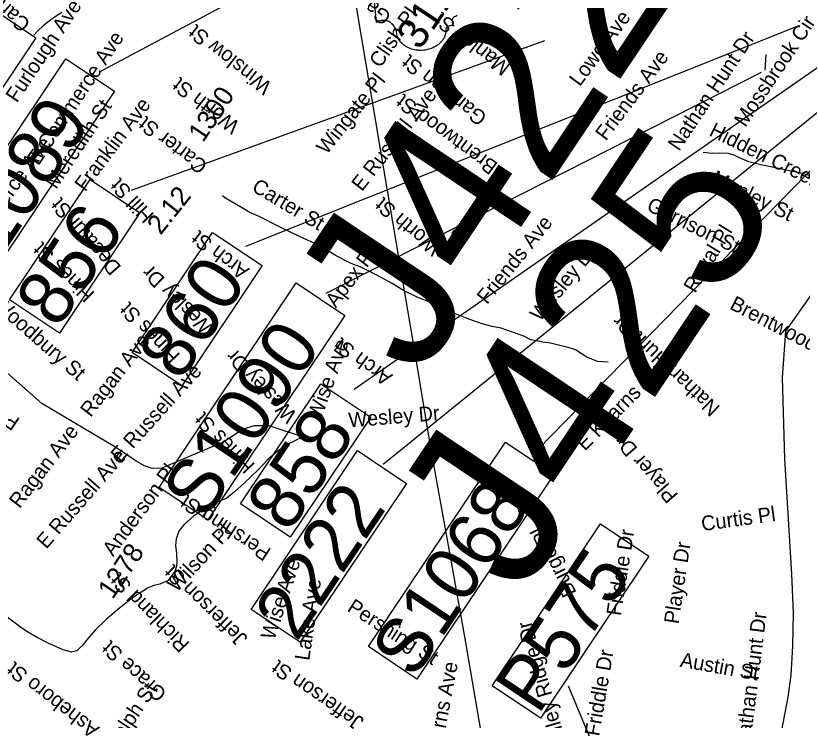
# Model space of a CAD drawing. Extents: x 1716282 to 1717158, y 799307 to 801078.
# Drawn here: x 1716607.4 to 1716680.6, y 799385.8 to 799451.4 of the extents above; entities that cross this region are included whole.
import ezdxf

# ---------------------------------------------------------------- set-up
doc = ezdxf.new("R2010")
doc.units = 0
for name, color, linetype in [('Exist Hydrographic Misc Water Feature', 7, 'Continuous'), ('Exist Road Non-System Structure Non-Sys Other Number Label', 7, 'Continuous'), ('Exist Road Non-System Type 51 Label', 7, 'Continuous'), ('Exist Road Primary Interstate Structure Cantilever Sign Number Label', 7, 'Continuous'), ('Exist Road Primary Interstate Structure Ovrhead Sign CELL', 7, 'Continuous'), ('Exist Road Primary US Shield CELL', 7, 'Continuous'), ('Exist Road Primary US Shield Number Label', 7, 'Continuous'), ('Exist Road Primary US Structure Ovrhead Sign CELL', 7, 'Continuous'), ('Exist Road Primary US Structure Pipe Number Label', 7, 'Continuous'), ('Exist Road Primary US Structure Standard Bridge Number Label', 7, 'Continuous'), ('Exist Road Secondary Mileage Tenths English Label', 7, 'Continuous'), ('Exist Road Secondary Type 51 Number Label', 7, 'Continuous'), ('Exist Utilities Electrical Transmission Line', 7, 'Continuous')]:
    doc.layers.add(name, color=color, linetype=linetype)

msp = doc.modelspace()

# ---------------------------------------------------------------- linework, layer by layer
at = {"layer": 'Exist Hydrographic Misc Water Feature'}
for points in [[(1716611.684, 799451.659), (1716610.792, 799451.073), (1716609.988, 799450.461), (1716609.419, 799449.937), (1716609.092, 799449.564)], [(1716692.169, 799435.567), (1716691.015, 799435.266), (1716690.298, 799435.193), (1716689.237, 799435.286), (1716686.84, 799435.273), (1716684.022, 799435.828), (1716682.215, 799436.217), (1716680.628, 799436.671), (1716678.821, 799437.061), (1716676.606, 799437.52), (1716675.619, 799437.773), (1716674.739, 799438.129), (1716674.251, 799438.392), (1716673.722, 799438.544), (1716672.86, 799438.568), (1716672.216, 799438.551), (1716671.365, 799438.642)], [(1716662.52, 799419.11), (1716661.547, 799419.178), (1716660.553, 799419.574), (1716659.483, 799420.269), (1716658.818, 799420.48), (1716657.92, 799420.707), (1716657.197, 799420.883), (1716656.45, 799420.973), (1716655.341, 799421.202), (1716654.695, 799421.54), (1716652.571, 799422.288), (1716651.728, 799422.442), (1716650.806, 799422.685), (1716649.555, 799423.118), (1716648.001, 799423.724), (1716646.961, 799424.258), (1716646.096, 799424.639), (1716644.815, 799425.128), (1716643.502, 799425.778), (1716642.367, 799426.482), (1716641.135, 799427.147), (1716639.456, 799427.979), (1716638.622, 799428.302), (1716637.934, 799428.632), (1716637.054, 799429.093), (1716636.384, 799429.551), (1716635.656, 799429.977), (1716633.879, 799430.77), (1716632.015, 799431.693), (1716629.991, 799432.69), (1716629.19, 799433.06), (1716628.35, 799433.527), (1716626.872, 799434.397), (1716626.648, 799434.584)], [(1716634.283, 799412.094), (1716631.001, 799413.172), (1716629.589, 799413.174), (1716628.557, 799412.863), (1716626.769, 799411.704), (1716621.009, 799409.256), (1716620.1, 799409.217), (1716619.381, 799409.463), (1716618.622, 799409.912), (1716616.792, 799411.137), (1716609.838, 799415.261), (1716604.726, 799419.771), (1716601.769, 799420.773), (1716598.43, 799420.566), (1716594.486, 799421.653), (1716591.302, 799423.243), (1716585.392, 799426.833), (1716582.572, 799429.941), (1716580.814, 799430.996), (1716580.091, 799431.043)], [(1716634.228, 799412.206), (1716633.177, 799411.687), (1716632.68, 799411.459), (1716631.736, 799410.787), (1716630.876, 799410.041), (1716630.002, 799409.128), (1716628.662, 799407.846), (1716627.768, 799407.051), (1716627.039, 799406.459), (1716625.859, 799405.968), (1716623.987, 799404.82), (1716623.078, 799404.003), (1716622.62, 799403.436), (1716622.346, 799402.675), (1716622.274, 799402.056), (1716622.356, 799401.3), (1716622.394, 799400.534), (1716622.366, 799400.133), (1716622.208, 799399.643), (1716621.594, 799398.798), (1716620.802, 799398.461), (1716620.262, 799398.338), (1716619.664, 799398.079), (1716618.359, 799397.249), (1716617.085, 799396.257), (1716615.809, 799395.161), (1716614.824, 799394.184), (1716614.001, 799393.236), (1716613.65, 799392.773), (1716613.349, 799392.486), (1716613.081, 799392.249), (1716612.604, 799392.117), (1716611.81, 799392.343), (1716610.489, 799392.93), (1716609.336, 799393.505), (1716608.443, 799394.047), (1716607.844, 799394.457), (1716605.562, 799396.154)]]:
    msp.add_lwpolyline(points, dxfattribs=at)
at = {"layer": 'Exist Road Primary Interstate Structure Cantilever Sign Number Label'}
msp.add_lwpolyline([(1716592.464, 799433.288), (1716605.07, 799452.122), (1716609.274, 799449.308), (1716596.669, 799430.474)], close=True, dxfattribs=at)
at = {"layer": 'Exist Road Primary Interstate Structure Ovrhead Sign CELL'}
msp.add_line((1716683.741, 799439.418), (1716655.978, 799410.97), dxfattribs=at)
msp.add_lwpolyline([(1716640.223, 799392.638), (1716652.966, 799411.677), (1716657.474, 799408.659), (1716644.731, 799389.62)], close=True, dxfattribs=at)
at = {"layer": 'Exist Road Primary US Shield CELL'}
msp.add_lwpolyline([(1716648.49, 799451.372), (1716648.381, 799451.309), (1716648.175, 799451.218), (1716648.12, 799451.188), (1716648.096, 799451.167), (1716648.052, 799451.108), (1716648.026, 799451.042), (1716648.01, 799450.968), (1716648.005, 799450.919), (1716648.005, 799450.851), (1716648.009, 799450.796), (1716648.021, 799450.724), (1716648.036, 799450.67), (1716648.048, 799450.629), (1716648.088, 799450.537), (1716648.111, 799450.499), (1716648.143, 799450.454), (1716648.197, 799450.397), (1716648.103, 799450.43), (1716648.034, 799450.442), (1716647.971, 799450.445), (1716647.911, 799450.444), (1716647.83, 799450.434), (1716647.765, 799450.419), (1716647.693, 799450.397), (1716647.628, 799450.367), (1716647.579, 799450.34), (1716647.539, 799450.311), (1716647.497, 799450.273), (1716647.469, 799450.237), (1716647.448, 799450.206), (1716647.43, 799450.156), (1716647.433, 799450.071), (1716647.434, 799449.99), (1716647.431, 799449.906), (1716647.421, 799449.809), (1716647.41, 799449.741), (1716647.393, 799449.663), (1716647.369, 799449.574), (1716647.336, 799449.482), (1716647.298, 799449.39), (1716647.262, 799449.311), (1716647.218, 799449.23), (1716647.174, 799449.16), (1716647.125, 799449.089), (1716647.075, 799449.025), (1716647.016, 799448.952), (1716646.937, 799448.864), (1716646.865, 799448.796), (1716646.785, 799448.727), (1716646.7, 799448.658), (1716646.602, 799448.589), (1716646.473, 799448.506), (1716646.378, 799448.453), (1716646.219, 799448.375), (1716646.015, 799448.294), (1716645.847, 799448.242), (1716645.717, 799448.21), (1716645.512, 799448.171), (1716645.383, 799448.154), (1716645.162, 799448.139), (1716645.009, 799448.137), (1716644.901, 799448.142), (1716644.731, 799448.157), (1716644.628, 799448.172), (1716644.482, 799448.2), (1716644.353, 799448.231), (1716644.233, 799448.265), (1716644.159, 799448.29), (1716644.033, 799448.339), (1716643.945, 799448.377), (1716643.829, 799448.434), (1716643.711, 799448.501), (1716643.606, 799448.569), (1716643.522, 799448.63), (1716643.428, 799448.707), (1716643.332, 799448.795), (1716643.255, 799448.877), (1716643.201, 799448.939), (1716643.139, 799449.02), (1716643.075, 799449.116), (1716643.018, 799449.215), (1716642.975, 799449.302), (1716642.933, 799449.404), (1716642.902, 799449.497), (1716642.875, 799449.61), (1716642.855, 799449.721), (1716642.846, 799449.818), (1716642.823, 799449.94), (1716642.805, 799450.008), (1716642.775, 799450.096), (1716642.743, 799450.171), (1716642.712, 799450.234), (1716642.663, 799450.323), (1716642.623, 799450.384), (1716642.557, 799450.471), (1716642.506, 799450.527), (1716642.438, 799450.594), (1716642.371, 799450.653), (1716642.282, 799450.718), (1716642.205, 799450.766), (1716642.11, 799450.816), (1716642.014, 799450.856), (1716641.926, 799450.886), (1716641.82, 799450.911), (1716641.739, 799450.923), (1716641.622, 799450.93), (1716641.508, 799450.928), (1716641.406, 799450.914), (1716641.312, 799450.895), (1716641.233, 799450.869), (1716641.161, 799450.842), (1716641.078, 799450.803), (1716641.005, 799450.761), (1716640.963, 799450.732), (1716640.8, 799452.696)], dxfattribs=at)
at = {"layer": 'Exist Road Primary US Structure Ovrhead Sign CELL'}
for p, q in [((1716643.573, 799461.232), (1716615.223, 799446.15)), ((1716677.151, 799446.297), (1716677.241, 799447.762)), ((1716676.775, 799446.089), (1716636.262, 799425.501))]:
    msp.add_line(p, q, dxfattribs=at)
for points in [[(1716599.331, 799428.313), (1716612.075, 799447.352), (1716616.583, 799444.335), (1716603.84, 799425.296)], [(1716620.762, 799407.449), (1716633.505, 799426.488), (1716638.014, 799423.471), (1716625.27, 799404.432)]]:
    msp.add_lwpolyline(points, close=True, dxfattribs=at)
at = {"layer": 'Exist Road Primary US Structure Pipe Number Label'}
msp.add_line((1716674.439, 799352.144), (1716658.834, 799388.944), dxfattribs=at)
msp.add_lwpolyline([(1716651.738, 799388.997), (1716661.815, 799404.053), (1716666.309, 799401.045), (1716656.232, 799385.989)], close=True, dxfattribs=at)
at = {"layer": 'Exist Road Primary US Structure Standard Bridge Number Label'}
for p, q in [((1716680.183, 799450.387), (1716628.78, 799429.868)), ((1716686.891, 799449.917), (1716638.887, 799416.575)), ((1716656.608, 799449.038), (1716618.161, 799435.086)), ((1716687.045, 799446.435), (1716641.591, 799409.591))]:
    msp.add_line(p, q, dxfattribs=at)
for points in [[(1716606.841, 799424.91), (1716614.333, 799436.105), (1716618.962, 799433.007), (1716611.469, 799421.813)], [(1716618.229, 799420.001), (1716625.721, 799431.195), (1716630.35, 799428.097), (1716622.857, 799416.903)], [(1716628.318, 799405.913), (1716635.81, 799417.107), (1716640.439, 799414.009), (1716632.947, 799402.815)], [(1716629.316, 799396.086), (1716639.218, 799410.879), (1716643.774, 799407.83), (1716633.872, 799393.036)]]:
    msp.add_lwpolyline(points, close=True, dxfattribs=at)
at = {"layer": 'Exist Utilities Electrical Transmission Line'}
for points in [[(1716665.164, 799344.443), (1716665.563, 799347.513), (1716666.118, 799351.428), (1716663.285, 799358.348), (1716660.01, 799365.081), (1716656.683, 799371.286), (1716651.135, 799382.119), (1716649.283, 799393.013), (1716647.919, 799400.679), (1716645.991, 799411.31), (1716644.572, 799419.966), (1716643.666, 799425.239), (1716641.374, 799438.762), (1716638.601, 799455.36), (1716638.051, 799459.861), (1716636.812, 799466.701), (1716635.068, 799476.572), (1716633.977, 799482.851), (1716632.367, 799492.558)], [(1716680.26, 799334.339), (1716680.764, 799335.057), (1716680.185, 799337.535), (1716678.331, 799344.799), (1716676.348, 799350.042), (1716675.432, 799352.434), (1716672.456, 799359.805), (1716671.861, 799361.346), (1716670.155, 799367.243), (1716673.875, 799374.217), (1716676.633, 799379.291), (1716678.11, 799382.043), (1716678.698, 799384.843), (1716679.28, 799387.925), (1716679.571, 799389.979), (1716679.706, 799392.689), (1716679.774, 799395.79), (1716679.635, 799399.371), (1716678.984, 799410.108), (1716678.759, 799417.692), (1716679.055, 799422.002), (1716682.293, 799426.601)]]:
    msp.add_lwpolyline(points, dxfattribs=at)

# ---------------------------------------------------------------- texts
at = {"layer": 'Exist Road Non-System Structure Non-Sys Other Number Label'}
for s, p in [('J422', (1716644.84, 799417.365)), ('J425', (1716654.363, 799397.163))]:
    msp.add_text(s, height=15.223, rotation=56.20506, dxfattribs=at).set_placement(p)
at = {"layer": 'Exist Road Non-System Type 51 Label'}
for s, rotation, p in [('Garrison St', 141.01369, (1716642.461, 799451.429)), ('Carter St', 139.04889, (1716608.876, 799450.747)), ('Furlough Ave', 56.20506, (1716607.511, 799443.186)), ('Clish Pl', 55.18721, (1716641.323, 799446.426)), ('Manley St', 142.44769, (1716653.532, 799446.763)), ('Lowe Ave', 53.49878, (1716659.89, 799444.705)), ('Mossbrook Cir', 56.20506, (1716675.294, 799440.917)), ('Winslow St', 141.77263, (1716631.328, 799444.988)), ('E Commerce Ave', 56.20506, (1716609.509, 799437.335)), ('Nathan Hunt Dr', 56.20506, (1716669.127, 799438.683)), ('Friends Ave', 53.03093, (1716662.323, 799439.646)), ('Garrison St', 141.90541, (1716651.361, 799442.084)), ('Wingate Pl', 51.45058, (1716636.335, 799438.358)), ('Worth St', 142.47176, (1716628.348, 799441.335)), ('E Russell Ave', 52.0765, (1716639.619, 799434.933)), ('Brentwood St', 143.52283, (1716652.36, 799437.579)), ('Meredith St', 56.20506, (1716611.172, 799435.14)), ('Franklin Ave', 52.92421, (1716613.866, 799434.907)), ('Carter St', 142.61798, (1716625.36, 799437.61)), ('Hidden Creek Te', 333.64208, (1716671.835, 799440.255)), ('E Commerce Ave', 53.35666, (1716602.205, 799427.873)), ('Lowe Ave', 52.45816, (1716647.97, 799429.445)), ('Manley St', 333.90828, (1716671.997, 799435.807)), ('Hill St', 133.17777, (1716620.368, 799432.855)), ('Carter St', 329.00998, (1716629.276, 799435.115)), ('Decatur St', 130.96538, (1716617.298, 799427.969)), ('Worth St', 139.86851, (1716647.054, 799429.946)), ('Garrison St', 333.64208, (1716666.007, 799433.301)), ('Friends Ave', 51.03779, (1716651.263, 799424.421)), ('Royal Pl', 58.95288, (1716670.627, 799425.47)), ('Arch St', 142.51633, (1716629.232, 799427.78)), ('Hines St', 135.81104, (1716614.833, 799425.545)), ('Apex Pl', 52.44501, (1716637.189, 799424.095)), ('Wesley Dr', 50.67357, (1716656.185, 799422.826)), ('Wesley Dr', 135.44369, (1716626.044, 799422.294)), ('Woodbury St', 318.71347, (1716605.164, 799424.347)), ('Hines St', 133.9789, (1716622.784, 799419.795)), ('Brentwood St', 332.62893, (1716673.746, 799424.121)), ('Nathan Hunt Dr', 136.5008, (1716673.026, 799414.93)), ('Ragan Ave', 52.11217, (1716614.382, 799413.912)), ('Wise Ave', 70.16439, (1716635.779, 799413.641)), ('Arch St', 143.83725, (1716642.558, 799417.907)), ('Wesley Dr', 133.10329, (1716633.66, 799414.249)), ('Pershing St', 146.20506, (1716607.897, 799413.807)), ('E Russell Ave', 47.92774, (1716617.126, 799409.689)), ('E Kearns Ave', 45.31337, (1716660.368, 799410.789)), ('Hines St', 133.9789, (1716629.736, 799409.568)), ('Wesley Dr', 4.58913, (1716638.418, 799413.042)), ('Ragan Ave', 52.34822, (1716607.762, 799405.426)), ('Player Dr', 131.02311, (1716669.105, 799406.75)), ('E Russell Ave', 48.92588, (1716610.249, 799401.657)), ('Anderson Pl', 53.23468, (1716616.465, 799400.952)), ('Pershing St', 146.83429, (1716631.271, 799401.674)), ('Curtis Pl', 7.89189, (1716671.285, 799403.384)), ('Wilson Pl', 46.73735, (1716622.39, 799397.626)), ('Burge Pl', 116.42851, (1716659.613, 799397.657)), ('Friddle Dr', 81.0064, (1716663.709, 799395.448)), ('Player Dr', 81.52202, (1716669.074, 799394.689)), ('Wise Ave', 71.4686, (1716631.451, 799393.175)), ('Jefferson St', 135.55183, (1716629.075, 799393.488)), ('Richland St', 134.65144, (1716623.671, 799392.931)), ('Lake Ave', 81.56169, (1716634.709, 799391.28)), ('Pershing St', 327.41472, (1716638.157, 799396.007)), ('Nathan Hunt Dr', 82.87203, (1716675.7, 799383.072)), ('Valley Ridge Dr', 106.12958, (1716658.886, 799382.837)), ('Grace St', 137.40259, (1716621.553, 799388.379)), ('Friddle Dr', 80.39387, (1716661.689, 799384.241)), ('Austin St', 349.89143, (1716669.153, 799390.767)), ('Asheboro St', 142.24786, (1716615.288, 799385.094)), ('Jefferson St', 145.31381, (1716639.907, 799385.878)), ('E Kearns Ave', 79.20571, (1716646.452, 799380.033)), ('Randolph St', 56.20506, (1716614.986, 799380.282))]:
    msp.add_text(s, height=1.3775, rotation=rotation, dxfattribs=at).set_placement(p)
at = {"layer": 'Exist Road Primary Interstate Structure Ovrhead Sign CELL'}
msp.add_text('S1068', height=5.075, rotation=56.20506, dxfattribs=at).set_placement((1716644.462, 799389.52))
at = {"layer": 'Exist Road Primary US Shield Number Label'}
msp.add_text('311', height=2.8275, rotation=56.20506, dxfattribs=at).set_placement((1716645.008, 799448.067))
at = {"layer": 'Exist Road Primary US Structure Ovrhead Sign CELL'}
for s, p in [('S1089', (1716603.57, 799425.196)), ('S1090', (1716625.001, 799404.332))]:
    msp.add_text(s, height=5.075, rotation=56.20506, dxfattribs=at).set_placement(p)
at = {"layer": 'Exist Road Primary US Structure Pipe Number Label'}
msp.add_text('P575', height=5.075, rotation=56.20506, dxfattribs=at).set_placement((1716656.02, 799386.188))
at = {"layer": 'Exist Road Primary US Structure Standard Bridge Number Label'}
for s, p in [('856', (1716611.332, 799422.123)), ('860', (1716622.72, 799417.214)), ('858', (1716632.809, 799403.126)), ('2222', (1716633.556, 799392.995))]:
    msp.add_text(s, height=5.075, rotation=56.20506, dxfattribs=at).set_placement(p)
at = {"layer": 'Exist Road Secondary Mileage Tenths English Label'}
msp.add_text('2.12', height=1.8125, rotation=51.43649, dxfattribs=at).set_placement((1716620.888, 799430.878))
at = {"layer": 'Exist Road Secondary Type 51 Number Label'}
for s, p in [('1300', (1716624.839, 799439.492)), ('1278', (1716616.43, 799396.968))]:
    msp.add_text(s, height=1.8125, rotation=56.20506, dxfattribs=at).set_placement(p)

doc.saveas('drawing.dxf')
